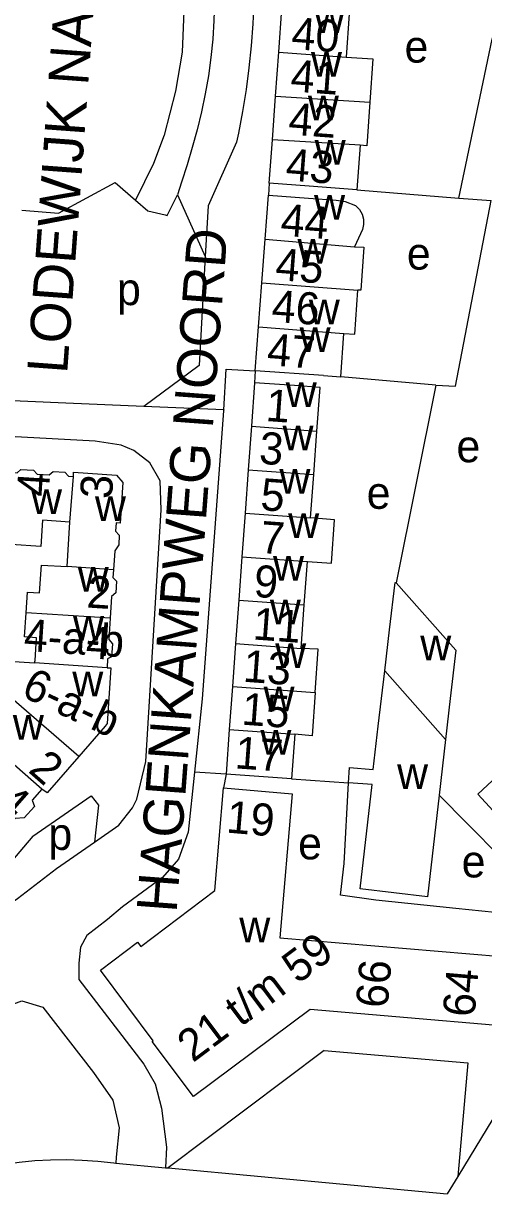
# Model space of a CAD drawing. Extents: x 159261 to 160849, y 382514 to 384534.
# Drawn here: x 160566.8 to 160624.3, y 382942.5 to 383087.7 of the extents above; entities that cross this region are included whole.
import ezdxf

# ---------------------------------------------------------------- set-up
doc = ezdxf.new("R2010")
doc.units = 0
for name, color, linetype in [('BLT_Basislijn', 7, 'Continuous'), ('BLT_Bebouwing', 7, 'Continuous'), ('BLT_Centroide', 7, 'Continuous'), ('BLT_Huisnummer', 7, 'Continuous'), ('BLT_Huisnummer_ tussenligend', 7, 'Continuous'), ('BLT_Huisnummer_reeks', 7, 'Continuous'), ('BLT_Onderverdeling_panden', 7, 'Continuous'), ('BLT_Straatnaam', 7, 'Continuous')]:
    doc.layers.add(name, color=color, linetype=linetype)

msp = doc.modelspace()

# ---------------------------------------------------------------- linework, layer by layer
at = {"layer": 'BLT_Basislijn'}
for p, q in [((160593.47, 383072.85), (160589.93, 383064.91)), ((160597.56, 383067.71), (160597.46, 383066.21)), ((160608.51, 383066.91), (160621.23, 383065.87)), ((160621.23, 383065.87), (160625.25, 383065.55)), ((160589.93, 383064.91), (160589.57, 383058.59)), ((160595.8, 383044.34), (160595.73, 383042.83)), ((160618.36, 383042.52), (160606.5, 383043.59)), ((160618.36, 383042.52), (160613.41, 383017.91)), ((160572.17, 383040.3), (160556.9, 383040.95)), ((160581.92, 383039.89), (160572.17, 383040.3)), ((160591.87, 383039.47), (160581.92, 383039.89)), ((160592.16, 382994.05), (160588.22, 382994.27)), ((160592.16, 382994.05), (160591.84, 382992.31)), ((160600.35, 382993.46), (160607.44, 382992.95)), ((160575.33, 382991.35), (160576.22, 382990.17)), ((160618.78, 382991.4), (160622.27, 382987.9)), ((160576.22, 382990.17), (160575.75, 382985.56)), ((160622.27, 382987.9), (160626.56, 382983.56)), ((160568.03, 382986.32), (160558.26, 382974.82)), ((160625.7, 382976.8), (160620.87, 382977.29)), ((160604.42, 382959.59), (160584.95, 382944.93)), ((160629.32, 382957.45), (160621.1, 382943.88)), ((160578.39, 382945.54), (160584.61, 382944.96)), ((160584.61, 382944.96), (160584.95, 382944.93)), ((160584.95, 382944.93), (160619.78, 382941.7)), ((160621.1, 382943.88), (160619.78, 382941.7))]:
    msp.add_line(p, q, dxfattribs=at)
for points in [[(160587.08, 383112.9), (160587.8, 383110.71), (160588.44, 383108.5), (160589, 383106.27), (160589.48, 383104.02), (160589.89, 383101.75), (160590.21, 383099.48), (160590.46, 383097.19), (160590.63, 383094.89), (160590.72, 383092.59), (160590.72, 383090.29), (160590.65, 383087.99), (160590.5, 383085.7), (160590.27, 383083.41), (160589.96, 383081.13), (160589.57, 383078.86), (160589.1, 383076.61), (160588.55, 383074.37), (160587.93, 383072.16), (160587.29, 383070.02), (160586.62, 383067.83), (160586.1, 383066.26)], [(160595.04, 383104.06), (160595.32, 383101.32), (160595.52, 383098.58), (160595.64, 383095.83), (160595.67, 383093.08), (160595.63, 383090.34), (160595.51, 383087.59), (160595.31, 383084.85), (160595.02, 383082.11), (160594.66, 383079.39), (160594.22, 383076.67), (160593.71, 383073.97), (160593.47, 383072.85)], [(160621.23, 383065.87), (160623.87, 383078.53), (160625.39, 383085.68), (160627.98, 383093.98), (160629.41, 383098.07)], [(160586.91, 383089.16), (160586.68, 383084.05), (160585.85, 383079.19), (160584.42, 383073.73), (160583.12, 383070.17), (160580.88, 383065.6)], [(160566.67, 383064.38), (160571.23, 383063.99), (160578.31, 383067.82), (160580.88, 383065.6)], [(160580.88, 383065.6), (160582.42, 383064.27), (160584.57, 383063.77)], [(160584.57, 383063.77), (160584.83, 383063.71), (160586.1, 383066.26)], [(160586.1, 383066.26), (160589.57, 383058.59)], [(160618.36, 383042.52), (160620.8, 383042.42), (160625.25, 383065.55)], [(160589.57, 383058.59), (160588.79, 383045), (160581.92, 383039.89)], [(160591.87, 383039.47), (160592.18, 383044.52), (160595.8, 383044.34)], [(160591.87, 383039.47), (160591.86, 383039.34), (160589.17, 383003.41), (160588.22, 382994.27)], [(160575.75, 382985.56), (160578.79, 382987.66), (160580.5, 382989.83), (160581.01, 382990.93), (160582.15, 382995.6), (160584.06, 383026.99), (160583.92, 383030.62), (160582.65, 383032.85), (160580.64, 383034.38), (160579.05, 383035.07), (160575.81, 383035.54), (160540.48, 383037.46), (160538.04, 383037.35), (160535.22, 383035.04), (160500, 383003.6), (160396.88, 382912.71)], [(160588.22, 382994.27), (160587.43, 382986.81), (160586.22, 382983.42), (160584.21, 382981.15), (160579.22, 382977.5), (160577.35, 382975.91), (160574.79, 382973.9), (160573.98, 382972.48), (160573.77, 382970.45), (160573.77, 382968.42), (160581.89, 382957.86), (160583.31, 382955.43), (160584.12, 382952.38), (160584.73, 382947.51), (160584.61, 382944.96)], [(160620.87, 382977.29), (160610.88, 382978.32), (160606.45, 382978.96), (160606.93, 382982.89), (160607.44, 382992.95)], [(160568.03, 382986.32), (160575.33, 382991.35)], [(160558.73, 382973.52), (160566.12, 382978.55), (160570.98, 382982.28), (160575.75, 382985.56)], [(160545.76, 382953.11), (160548.72, 382954.9), (160550.69, 382956.43), (160551.88, 382957.01), (160558.9, 382961.57), (160559.26, 382961.65), (160562.82, 382964.36), (160566.67, 382965.78), (160569.31, 382964.97), (160575.6, 382956.85), (160578.03, 382953.4), (160578.84, 382949.95), (160578.44, 382946.29), (160578.39, 382945.54)], [(160604.42, 382959.59), (160622.37, 382958.05), (160621.1, 382943.88)], [(160553.05, 382942.17), (160554.85, 382942.88), (160556.71, 382943.53), (160558.6, 382944.11), (160560.5, 382944.61), (160562.43, 382945.04), (160564.37, 382945.38), (160566.33, 382945.65), (160568.29, 382945.84), (160570.26, 382945.94), (160572.23, 382945.97), (160574.21, 382945.92), (160576.17, 382945.78), (160578.14, 382945.57), (160578.39, 382945.54)]]:
    msp.add_lwpolyline(points, dxfattribs=at)
at = {"layer": 'BLT_Bebouwing'}
for p, q in [((160598.75, 383084.04), (160599.14, 383089.48)), ((160607.55, 383088.82), (160607.17, 383083.42)), ((160598.35, 383078.59), (160598.75, 383084.04)), ((160597.95, 383073.15), (160598.35, 383078.59)), ((160596.63, 383055.28), (160597.04, 383060.74)), ((160596.21, 383049.81), (160596.63, 383055.28)), ((160608.24, 383048.9), (160608.62, 383054.37)), ((160595.8, 383044.34), (160596.21, 383049.81)), ((160604.32, 383043.74), (160595.8, 383044.34)), ((160595.33, 383037.41), (160594.94, 383031.99)), ((160603.11, 383031.4), (160603.51, 383036.82)), ((160594.94, 383031.99), (160594.54, 383026.57)), ((160602.72, 383025.98), (160603.11, 383031.4)), ((160594.54, 383026.57), (160594.14, 383021.15)), ((160572.31, 383019.91), (160572.67, 383025.47)), ((160594.14, 383021.15), (160593.75, 383015.73)), ((160601.93, 383015.14), (160602.32, 383020.56)), ((160593.75, 383015.73), (160593.35, 383010.31)), ((160601.53, 383009.72), (160601.93, 383015.14)), ((160593.35, 383010.31), (160592.96, 383004.98)), ((160592.96, 383004.98), (160592.57, 382999.6)), ((160592.57, 382999.6), (160592.16, 382994.05)), ((160600.75, 382999.01), (160600.35, 382993.46)), ((160600.35, 382993.46), (160592.16, 382994.05))]:
    msp.add_line(p, q, dxfattribs=at)
for points in [[(160607.17, 383083.42), (160610.51, 383083.21), (160610.12, 383077.81)], [(160610.12, 383077.81), (160609.73, 383072.38), (160608.91, 383072.46)], [(160597.56, 383067.71), (160597.95, 383073.15)], [(160608.91, 383072.46), (160608.51, 383066.91)], [(160608.51, 383066.91), (160602.54, 383067.34), (160597.56, 383067.71)], [(160597.04, 383060.74), (160597.46, 383066.21)], [(160597.46, 383066.21), (160602.44, 383065.85), (160605.92, 383065.6), (160607.04, 383065.42), (160608.32, 383064.93), (160608.81, 383064.43), (160609.14, 383063.85), (160609.31, 383063.25), (160609.34, 383062.58), (160609.2, 383061.94), (160608.19, 383059.8)], [(160608.19, 383059.8), (160609.37, 383059.74), (160608.98, 383054.37), (160608.62, 383054.37)], [(160606.5, 383043.59), (160606.88, 383049)], [(160606.88, 383049), (160608.24, 383048.9)], [(160604.32, 383043.74), (160606.5, 383043.59)], [(160595.73, 383042.83), (160595.33, 383037.41)], [(160603.51, 383036.82), (160603.91, 383042.26), (160600.71, 383042.48), (160595.73, 383042.83)], [(160563.24, 383031.8), (160566.08, 383031.62), (160566.56, 383032.04), (160568.12, 383031.94), (160568.57, 383031.44), (160570.08, 383031.34), (160570.59, 383031.79), (160572.05, 383031.7), (160572.48, 383031.2), (160573.1, 383031.16)], [(160573.1, 383031.16), (160573.14, 383031.67), (160578.47, 383031.33), (160579.28, 383030.4), (160578.95, 383025.34), (160578.45, 383025.37), (160578.38, 383024.35), (160578.84, 383023.83), (160578.76, 383022.62), (160578.27, 383021.89), (160578.12, 383019.53)], [(160572.67, 383025.47), (160569.24, 383025.69), (160569.03, 383022.44), (160565.34, 383022.68), (160565.23, 383020.91), (160562.55, 383021.08)], [(160602.32, 383020.56), (160605.31, 383020.34), (160605.69, 383025.73), (160602.72, 383025.98)], [(160567.2, 383014.17), (160567.39, 383016.73), (160568.88, 383016.64), (160569.11, 383020.11), (160572.31, 383019.91)], [(160578.12, 383019.53), (160578.05, 383018.57), (160578.48, 383018.08), (160578.39, 383016.64), (160577.87, 383016.18), (160577.69, 383013.5)], [(160612.57, 383012.05), (160613.26, 383017.93), (160613.41, 383017.91)], [(160613.41, 383017.91), (160620.85, 383009.49), (160620.16, 383003.47)], [(160568.27, 383007.9), (160568.34, 383008.19), (160568.52, 383011.05), (160567.02, 383011.15), (160567.2, 383014.17)], [(160577.69, 383013.5), (160577.52, 383010.81), (160577.99, 383010.28), (160577.88, 383008.67), (160577.38, 383008.42), (160577.31, 383007.31)], [(160611.97, 383006.92), (160612.57, 383012.05)], [(160603.28, 383004.23), (160603.65, 383009.62), (160601.53, 383009.72)], [(160557.94, 383006.61), (160557.31, 383008.61), (160568.27, 383007.9)], [(160577.31, 383007.31), (160577.79, 383007.28), (160577.34, 383000.34), (160577.08, 383000), (160573.77, 382996.22)], [(160607.44, 382992.95), (160607.58, 382994.85), (160610.54, 382994.63), (160611.17, 383000), (160611.97, 383006.92)], [(160603.28, 383004.23), (160602.9, 382998.81), (160600.75, 382999.01)], [(160620.16, 383003.47), (160619.58, 382998.37)], [(160619.58, 382998.37), (160618.78, 382991.4)], [(160573.77, 382996.22), (160569.82, 382991.7), (160569.17, 382992.18)], [(160618.78, 382991.4), (160617.33, 382978.74), (160608.89, 382979.75), (160610.4, 382992.74), (160607.44, 382992.95)], [(160631.75, 382982.69), (160623.59, 382991.52), (160626.02, 382993.77), (160630.52, 382988.9), (160632.59, 382988.6)], [(160569.17, 382992.18), (160567.96, 382990.79), (160568.23, 382990.01), (160566.98, 382988.59), (160565.84, 382988.51), (160565.35, 382987.95)], [(160637.67, 382961.71), (160602.65, 382964.7), (160588.12, 382953.83), (160582.95, 382960.71), (160583.07, 382960.8), (160576.51, 382969.6), (160581.1, 382973.08), (160581.52, 382972.56), (160590.75, 382979.53), (160591.84, 382992.31)], [(160591.84, 382992.31), (160600.42, 382991.58), (160598.89, 382973.64), (160638.4, 382970.3)]]:
    msp.add_lwpolyline(points, dxfattribs=at)
at = {"layer": 'BLT_Onderverdeling_panden'}
for p, q in [((160598.75, 383084.04), (160607.17, 383083.42)), ((160598.35, 383078.59), (160610.12, 383077.81)), ((160608.91, 383072.46), (160597.95, 383073.15)), ((160597.04, 383060.74), (160608.19, 383059.8)), ((160596.63, 383055.28), (160608.62, 383054.37)), ((160596.21, 383049.81), (160606.88, 383049)), ((160595.33, 383037.41), (160603.51, 383036.82)), ((160594.94, 383031.99), (160603.11, 383031.4)), ((160572.67, 383025.47), (160573.1, 383031.16)), ((160594.54, 383026.57), (160602.72, 383025.98)), ((160594.14, 383021.15), (160602.32, 383020.56)), ((160578.12, 383019.53), (160572.31, 383019.91)), ((160593.75, 383015.73), (160601.93, 383015.14)), ((160577.69, 383013.5), (160567.2, 383014.17)), ((160593.35, 383010.31), (160601.53, 383009.72)), ((160577.31, 383007.31), (160568.27, 383007.9)), ((160619.58, 382998.37), (160611.97, 383006.92)), ((160592.96, 383004.98), (160603.28, 383004.23)), ((160573.77, 382996.22), (160565.37, 383003.53)), ((160569.17, 382992.18), (160560.09, 383000.11)), ((160592.57, 382999.6), (160600.75, 382999.01))]:
    msp.add_line(p, q, dxfattribs=at)

# ---------------------------------------------------------------- texts
at = {"layer": 'BLT_Centroide'}
for s, p in [('w', (160603.16, 383086.44)), ('e', (160614.45, 383082.76)), ('w', (160602.77, 383081)), ('w', (160602.38, 383075.56)), ('w', (160603.23, 383070.03)), ('w', (160603.16, 383063.16)), ('w', (160601.08, 383057.69)), ('e', (160614.74, 383056.95)), ('p', (160578.55, 383052.52)), ('w', (160602.5, 383050.13)), ('w', (160601.35, 383046.69)), ('w', (160599.62, 383039.81)), ('w', (160599.22, 383034.41)), ('e', (160620.93, 383032.93)), ('w', (160598.83, 383029)), ('w', (160567.82, 383026.47)), ('e', (160609.72, 383027.12)), ('w', (160575.8, 383025.59)), ('w', (160599.92, 383023.47)), ('w', (160598.03, 383018.16)), ('w', (160573.65, 383016.81)), ('w', (160597.64, 383012.72)), ('w', (160573.06, 383010.69)), ('w', (160598.3, 383007.28)), ('w', (160616.41, 383008.22)), ('w', (160572.97, 383003.73)), ('w', (160596.85, 383001.88)), ('w', (160565.55, 382998.32)), ('w', (160596.45, 382996.47)), ('w', (160613.52, 382992.19)), ('p', (160569.98, 382984.59)), ('e', (160601.16, 382983.41)), ('e', (160621.58, 382981.16)), ('w', (160593.82, 382973.06))]:
    msp.add_text(s, height=4, dxfattribs=at).set_placement(p)
at = {"layer": 'BLT_Huisnummer'}
for s, rotation, p in [('40', 355.8314, (160600.24, 383084.46)), ('41', 355.832, (160600.13, 383079.18)), ('42', 355.8017, (160599.87, 383073.8)), ('43', 355.6587, (160599.52, 383068.09)), ('44', 355.6596, (160598.88, 383061.2)), ('45', 355.6606, (160598.24, 383055.66)), ('46', 355.9851, (160597.77, 383050.45)), ('47', 355.8173, (160597.2, 383045.03)), ('1', 355.8173, (160597.04, 383038.08)), ('4', 86.3034, (160570.02, 383028.56)), ('3', 86.2904, (160577.91, 383028.29)), ('5', 355.8178, (160596.38, 383026.97)), ('9', 355.8188, (160595.54, 383016.16)), ('2', 356.3025, (160574.7, 383014.82)), ('4', 356.3023, (160574.59, 383008.51)), ('13', 355.8193, (160594.21, 383005.57)), ('17', 355.8188, (160593.18, 382994.77)), ('2', 318.8118, (160567.34, 382994.39))]:
    msp.add_text(s, height=4, rotation=rotation, dxfattribs=at).set_placement(p)
at = {"layer": 'BLT_Huisnummer_ tussenligend'}
for s, rotation, p in [('3', 355.8173, (160596.21, 383032.76)), ('7', 355.8178, (160596.36, 383021.63)), ('11', 355.8188, (160595.43, 383010.84)), ('15', 355.8193, (160594.02, 383000.22)), ('4', 318.8118, (160563.18, 382990.14))]:
    msp.add_text(s, height=4, rotation=rotation, dxfattribs=at).set_placement(p)
at = {"layer": 'BLT_Huisnummer_reeks'}
for s, rotation, p in [('4-a-b', 356.2524, (160566.85, 383009.42)), ('6-a-b', 334.7986, (160566.44, 383003.83)), ('19', 355.1476, (160592.11, 382986.76)), ('21 t/m 59', 36.8156, (160588.02, 382957.99)), ('66', 85.1109, (160612.33, 382964.78)), ('64', 85.1109, (160623.18, 382963.66))]:
    msp.add_text(s, height=4, rotation=rotation, dxfattribs=at).set_placement(p)
at = {"layer": 'BLT_Straatnaam'}
for s, height, rotation, p in [('LODEWIJK NAPOLEONPLEIN', 5, 85.829, (160572.32, 383043.89)), ('HAGENKAMPWEG NOORD', 4.9999, 85.7178, (160585.98, 382976.69))]:
    msp.add_text(s, height=height, rotation=rotation, dxfattribs=at).set_placement(p)

doc.saveas('drawing.dxf')
